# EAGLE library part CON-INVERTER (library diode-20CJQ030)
Molex Miniatur connectors
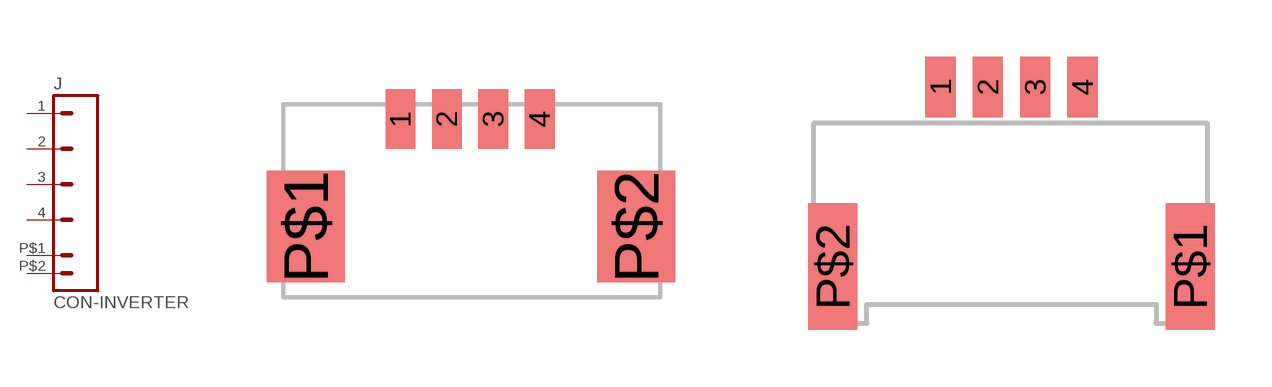
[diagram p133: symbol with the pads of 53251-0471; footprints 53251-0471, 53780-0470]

Designator prefix J

## CON-INVERTER-1  [53251-0471]
1  1  pas
2  2  pas
3  3  pas
4  4  pas
P$1  SHIELD  pas
P$2  SHIELD  pas

## CON-INVERTER-2  [53780-0470]
Pads as for 53251-0471

## Footprint 53251-0471 (pad centres in mm)
Molex Micro-Miniature 1.25mm Connectors
smd 0.8 x 1.6: 1 3.6,4.4; 2 4.85,4.4; 3 6.1,4.4; 4 7.35,4.4
smd 2.1 x 3: P$1 1.05,1.5; P$2 9.95,1.5

## Footprint 53780-0470 (pad centres in mm)
Molex Panel Mate 1.25mm Connectors Ultra Low Profile 53780-0470
smd 0.8 x 1.6: 1 -1.9,6.45; 2 -0.65,6.45; 3 0.6,6.45; 4 1.85,6.45
smd 1.3 x 3.35: P$1 4.7,1.7; P$2 -4.75,1.7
